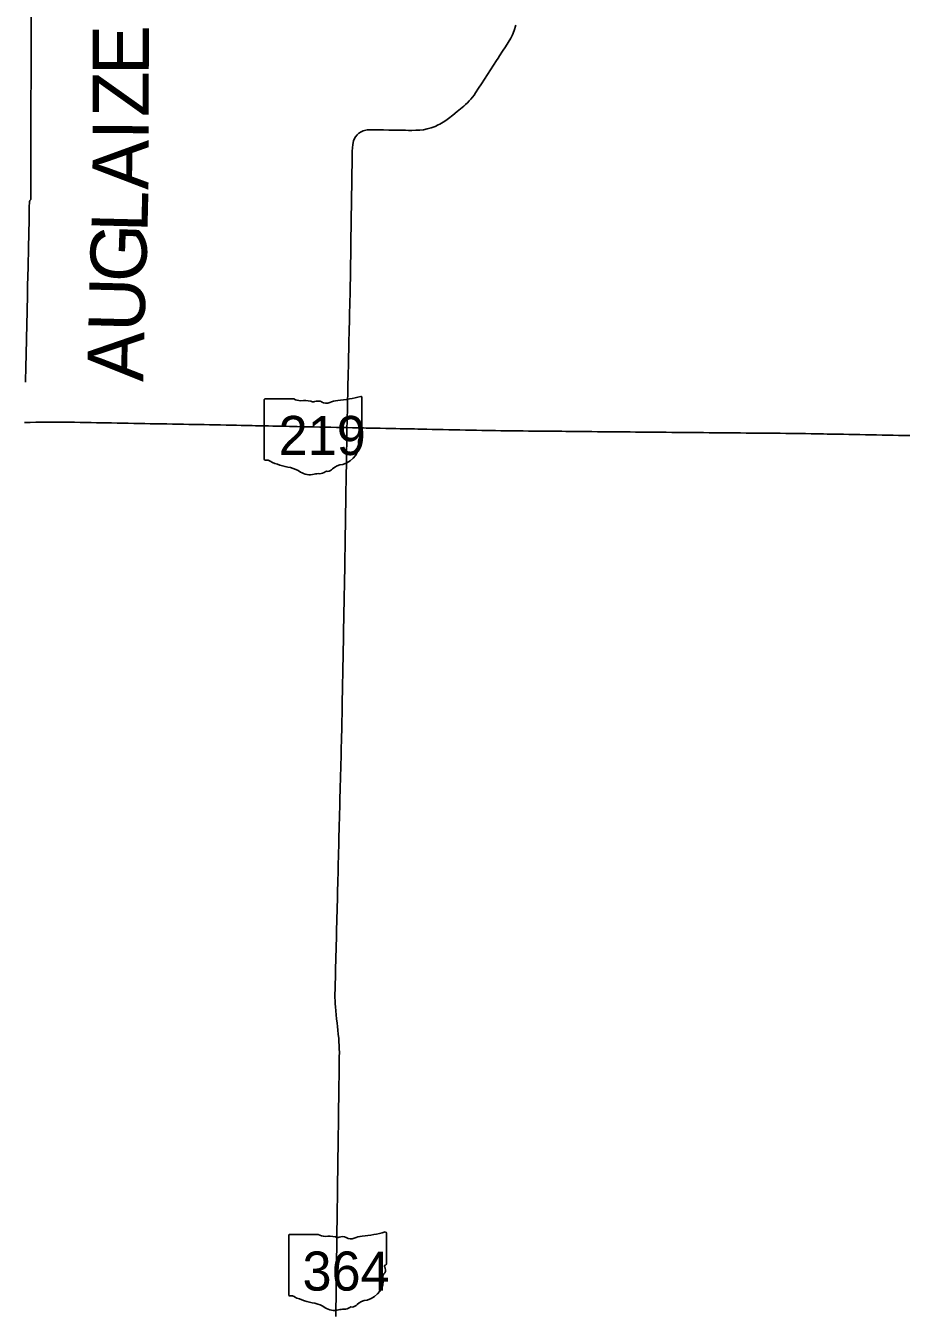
# Model space of a CAD drawing. Extents: x 0 to 34, y 0 to 22.
# Drawn here: x 4.2041 to 4.4563, y 19.2422 to 19.6111 of the extents above; entities that cross this region are included whole.
import ezdxf

# ---------------------------------------------------------------- set-up
doc = ezdxf.new("R2010")
doc.units = 0
for name, color, linetype in [('GM_X_County', 7, 'Continuous'), ('GM_X_County_Text', 7, 'Continuous'), ('GM_X_State_Location', 7, 'Continuous'), ('GM_X_State_Route', 7, 'Continuous'), ('GM_X_State_Shield', 7, 'Continuous')]:
    doc.layers.add(name, color=color, linetype=linetype)

msp = doc.modelspace()

# ---------------------------------------------------------------- linework, layer by layer
at = {"layer": 'GM_X_County'}
for points in [[(4.20566, 19.62427), (4.20556, 19.5614), (4.20547, 19.56133), (4.2054, 19.56127), (4.20535, 19.56121), (4.20531, 19.56115), (4.20527, 19.56107), (4.20523, 19.56097), (4.20519, 19.56086), (4.20517, 19.56076), (4.20515, 19.56061), (4.20512, 19.56041), (4.2051, 19.56013), (4.20508, 19.5598), (4.20502, 19.55558), (4.2049, 19.54762), (4.2048, 19.54209), (4.2046, 19.53666), (4.20455, 19.53397), (4.20448, 19.52949), (4.2044, 19.52543), (4.20431, 19.52169), (4.20417, 19.51684), (4.2041, 19.51363), (4.20398, 19.50904)], [(4.20398, 19.50904), (4.2041, 19.51363), (4.20417, 19.51684), (4.20431, 19.52169), (4.2044, 19.52543), (4.20448, 19.52949), (4.20455, 19.53397), (4.2046, 19.53666), (4.2048, 19.54209), (4.2049, 19.54762), (4.20502, 19.55558), (4.20508, 19.5598), (4.2051, 19.56013), (4.20512, 19.56041), (4.20515, 19.56061), (4.20517, 19.56076), (4.20519, 19.56086), (4.20523, 19.56097), (4.20527, 19.56107), (4.20531, 19.56115), (4.20535, 19.56121), (4.2054, 19.56127), (4.20547, 19.56133), (4.20556, 19.5614), (4.20566, 19.62427)]]:
    msp.add_lwpolyline(points, dxfattribs=at)
at = {"layer": 'GM_X_State_Route'}
for points in [[(4.29608, 19.49608), (4.29611, 19.49766), (4.29615, 19.49924), (4.29619, 19.50082), (4.29622, 19.50241), (4.29626, 19.50399), (4.29629, 19.50557), (4.29633, 19.50715), (4.29637, 19.50873), (4.2964, 19.51031), (4.29644, 19.5119), (4.29648, 19.51348), (4.29651, 19.51506), (4.29655, 19.51664), (4.29659, 19.51822), (4.29662, 19.5198), (4.29666, 19.52139), (4.29669, 19.52297), (4.29673, 19.52455), (4.29677, 19.52613), (4.2968, 19.52771), (4.29684, 19.52929), (4.29687, 19.53087), (4.29691, 19.53246), (4.29695, 19.53404), (4.29698, 19.53562), (4.29702, 19.53711), (4.29705, 19.53861), (4.29707, 19.54019), (4.2971, 19.54177), (4.29712, 19.54336), (4.29714, 19.54494), (4.29716, 19.54652), (4.29718, 19.5481), (4.29721, 19.54968), (4.29723, 19.55127), (4.29725, 19.55285), (4.29727, 19.55443), (4.29729, 19.55601), (4.29732, 19.55759), (4.29733, 19.55878), (4.29735, 19.55996), (4.29738, 19.56154), (4.2974, 19.56312), (4.29743, 19.5647), (4.29746, 19.56628), (4.29748, 19.56787), (4.29751, 19.56945), (4.29754, 19.57101), (4.29756, 19.57258), (4.29759, 19.5739), (4.29761, 19.57523), (4.29769, 19.57618), (4.29777, 19.57714), (4.29796, 19.57814), (4.2982, 19.57886), (4.29848, 19.57934), (4.29896, 19.57991), (4.29945, 19.58039), (4.30013, 19.58079), (4.30076, 19.58105), (4.30147, 19.58122), (4.30186, 19.5813), (4.30241, 19.58133), (4.30335, 19.58133), (4.30493, 19.58131), (4.30651, 19.58129), (4.30809, 19.58126), (4.30967, 19.58124), (4.31126, 19.58122), (4.31284, 19.5812), (4.31373, 19.58119), (4.31462, 19.58117), (4.31577, 19.58121), (4.31692, 19.58125), (4.31798, 19.58137), (4.31904, 19.58158), (4.32024, 19.58192), (4.3213, 19.5823), (4.32221, 19.58272), (4.32267, 19.58297), (4.32366, 19.58352), (4.32441, 19.58403), (4.32517, 19.58454), (4.32639, 19.58554), (4.32761, 19.58654), (4.32857, 19.58733), (4.32952, 19.58811), (4.33007, 19.58859), (4.3306, 19.58909), (4.33111, 19.58961), (4.33159, 19.59015), (4.33205, 19.59071), (4.33248, 19.5913), (4.33289, 19.5919), (4.33375, 19.59322), (4.33462, 19.59455), (4.33548, 19.59588), (4.33634, 19.5972), (4.3372, 19.59853), (4.33806, 19.59986), (4.33892, 19.60118), (4.33937, 19.60187), (4.33981, 19.60255), (4.34066, 19.60382), (4.3415, 19.60509), (4.34226, 19.60636), (4.34302, 19.60762), (4.34351, 19.60849), (4.34397, 19.6098), (4.34447, 19.6113)], [(4.20376, 19.49757), (4.20534, 19.49758), (4.20693, 19.4976), (4.20851, 19.49761), (4.21009, 19.49762), (4.21167, 19.49763), (4.21325, 19.49764), (4.21406, 19.49765), (4.21486, 19.49765), (4.21645, 19.49763), (4.21803, 19.4976), (4.21961, 19.49757), (4.22119, 19.49754), (4.22277, 19.49751), (4.22436, 19.49748), (4.22594, 19.49745), (4.2273, 19.49743), (4.22866, 19.4974), (4.23024, 19.49737), (4.23182, 19.49734), (4.23341, 19.49732), (4.23499, 19.49729), (4.23657, 19.49726), (4.23815, 19.49723), (4.23973, 19.4972), (4.24132, 19.49717), (4.2429, 19.49714), (4.24448, 19.49711), (4.24606, 19.49709), (4.24765, 19.49706), (4.24923, 19.49703), (4.25081, 19.497), (4.25219, 19.49697), (4.25357, 19.49695), (4.25516, 19.49692), (4.25674, 19.49688), (4.25832, 19.49685), (4.2599, 19.49682), (4.26148, 19.49679), (4.26306, 19.49676), (4.26441, 19.49673), (4.26575, 19.4967), (4.26733, 19.49667), (4.26891, 19.49664), (4.26984, 19.49662), (4.27077, 19.4966), (4.27235, 19.49657), (4.27359, 19.49654), (4.27483, 19.49651), (4.27641, 19.49648), (4.27799, 19.49645), (4.27957, 19.49642), (4.28068, 19.4964), (4.2818, 19.49637), (4.28338, 19.49634), (4.28427, 19.49632), (4.28515, 19.4963), (4.28673, 19.49627), (4.28831, 19.49624), (4.2899, 19.49621), (4.29148, 19.49617), (4.29306, 19.49614), (4.29457, 19.49611), (4.29608, 19.49608), (4.29766, 19.49605), (4.29924, 19.49601), (4.30082, 19.49598), (4.30162, 19.49596), (4.30242, 19.49595), (4.30401, 19.49592), (4.30559, 19.49588), (4.30717, 19.49585), (4.30875, 19.49582), (4.31003, 19.49579), (4.3113, 19.49576), (4.31289, 19.49573), (4.31447, 19.4957), (4.31542, 19.49568), (4.31638, 19.49566), (4.31735, 19.49564), (4.31893, 19.49561), (4.32051, 19.49557), (4.32209, 19.49554), (4.32367, 19.49551), (4.32525, 19.49547), (4.32683, 19.49544), (4.32842, 19.49541), (4.33, 19.49537), (4.33158, 19.49534), (4.33316, 19.49531), (4.33474, 19.49528), (4.33632, 19.49524), (4.33747, 19.49522), (4.33861, 19.4952), (4.34019, 19.49518), (4.34177, 19.49516), (4.34336, 19.49515), (4.34494, 19.49513), (4.34652, 19.49512), (4.3481, 19.4951), (4.34968, 19.49509), (4.35127, 19.49507), (4.35285, 19.49506), (4.35443, 19.49504), (4.35601, 19.49502), (4.35759, 19.49501), (4.35876, 19.495), (4.35992, 19.49499), (4.3615, 19.49497), (4.36308, 19.49495), (4.36467, 19.49494), (4.36625, 19.49492), (4.36783, 19.49491), (4.36941, 19.49489), (4.37078, 19.49488), (4.37215, 19.49487), (4.37373, 19.49485), (4.37531, 19.49483), (4.37625, 19.49483), (4.37719, 19.49482), (4.37877, 19.4948), (4.38, 19.49479), (4.38122, 19.49478), (4.38281, 19.49476), (4.38439, 19.49475), (4.38597, 19.49474), (4.38755, 19.49472), (4.38913, 19.49471), (4.3905, 19.4947), (4.39187, 19.49468), (4.39345, 19.49467), (4.39503, 19.49466), (4.39661, 19.49464), (4.3982, 19.49463), (4.39978, 19.49462), (4.40115, 19.4946), (4.40251, 19.49459), (4.4041, 19.49458), (4.40568, 19.49456), (4.40726, 19.49455), (4.40884, 19.49454), (4.41042, 19.49452), (4.41179, 19.49451), (4.41316, 19.4945), (4.41474, 19.49448), (4.41632, 19.49447), (4.41791, 19.49446), (4.41905, 19.49445), (4.42019, 19.49444), (4.42177, 19.49442), (4.42279, 19.49441), (4.4238, 19.49441), (4.42539, 19.49438), (4.4264, 19.49436), (4.42742, 19.49434), (4.429, 19.49431), (4.43002, 19.49429), (4.43104, 19.49428), (4.43262, 19.49425), (4.43364, 19.49423), (4.43465, 19.49421), (4.43623, 19.49418), (4.43725, 19.49416), (4.43827, 19.49415), (4.43985, 19.49412), (4.44144, 19.49409), (4.44302, 19.49406), (4.4446, 19.49403), (4.44618, 19.494), (4.44776, 19.49397), (4.44935, 19.49395), (4.45093, 19.49392), (4.45251, 19.49389), (4.45409, 19.49386), (4.45567, 19.49383), (4.45726, 19.49381)], [(4.29326, 19.32554), (4.29312, 19.32675), (4.29298, 19.32796), (4.29287, 19.32909), (4.29276, 19.33022), (4.29272, 19.33108), (4.29267, 19.33195), (4.29265, 19.33286), (4.29264, 19.33378), (4.29268, 19.33536), (4.29272, 19.33694), (4.29276, 19.33852), (4.2928, 19.34011), (4.29284, 19.34169), (4.29288, 19.34327), (4.29292, 19.34485), (4.29296, 19.34643), (4.293, 19.34801), (4.29304, 19.3496), (4.29308, 19.35118), (4.29312, 19.35276), (4.29316, 19.35434), (4.2932, 19.35592), (4.29324, 19.3575), (4.29328, 19.35909), (4.29332, 19.36067), (4.29336, 19.36225), (4.2934, 19.36383), (4.29344, 19.36541), (4.29347, 19.36683), (4.29351, 19.36825), (4.29355, 19.36983), (4.29359, 19.37141), (4.29363, 19.37299), (4.29367, 19.37458), (4.29371, 19.37616), (4.29375, 19.37774), (4.29379, 19.37932), (4.29384, 19.3809), (4.29388, 19.38248), (4.29392, 19.38407), (4.29396, 19.38565), (4.294, 19.38723), (4.29404, 19.38881), (4.29408, 19.39039), (4.29412, 19.39197), (4.29416, 19.39355), (4.2942, 19.39514), (4.29424, 19.39672), (4.29429, 19.3983), (4.29433, 19.39988), (4.29437, 19.40146), (4.29441, 19.40304), (4.29445, 19.40463), (4.29449, 19.40621), (4.29453, 19.40779), (4.29457, 19.40924), (4.29461, 19.41069), (4.29463, 19.41227), (4.29466, 19.41385), (4.29469, 19.41544), (4.29472, 19.41702), (4.29475, 19.4186), (4.29478, 19.42018), (4.29481, 19.42176), (4.29484, 19.42334), (4.29487, 19.42492), (4.2949, 19.42651), (4.29493, 19.42809), (4.29495, 19.42967), (4.29498, 19.43125), (4.29501, 19.43283), (4.29504, 19.43441), (4.29507, 19.436), (4.2951, 19.43758), (4.29513, 19.43916), (4.29516, 19.44074), (4.29519, 19.44232), (4.29522, 19.4439), (4.29525, 19.44549), (4.29528, 19.44707), (4.29531, 19.44865), (4.29534, 19.45023), (4.29536, 19.45176), (4.29539, 19.45328), (4.29542, 19.45487), (4.29544, 19.45645), (4.29547, 19.45803), (4.29549, 19.45961), (4.29552, 19.46119), (4.29554, 19.46278), (4.29557, 19.46436), (4.29559, 19.46594), (4.29562, 19.46752), (4.29565, 19.46911), (4.29567, 19.47069), (4.2957, 19.47227), (4.29572, 19.47385), (4.29575, 19.47543), (4.29577, 19.47702), (4.2958, 19.4786), (4.29582, 19.48018), (4.29585, 19.48176), (4.29587, 19.48334), (4.2959, 19.48493), (4.29592, 19.48651), (4.29595, 19.48809), (4.29597, 19.48967), (4.296, 19.49125), (4.29602, 19.49284), (4.29605, 19.49442), (4.29606, 19.49525), (4.29608, 19.49608)], [(4.29289, 19.24156), (4.29291, 19.24314), (4.29293, 19.24472), (4.29295, 19.24631), (4.29297, 19.24789), (4.29299, 19.24947), (4.29301, 19.25105), (4.29303, 19.25264), (4.29305, 19.25422), (4.29307, 19.2558), (4.2931, 19.25738), (4.29312, 19.25896), (4.29314, 19.26055), (4.29316, 19.26213), (4.29318, 19.26371), (4.2932, 19.26529), (4.29322, 19.26687), (4.29324, 19.26846), (4.29326, 19.27004), (4.29328, 19.27162), (4.2933, 19.2732), (4.29332, 19.27478), (4.29334, 19.27637), (4.29336, 19.27795), (4.29338, 19.27953), (4.2934, 19.28111), (4.29342, 19.28269), (4.29343, 19.28365), (4.29345, 19.28461), (4.29347, 19.28619), (4.29349, 19.28777), (4.29352, 19.28935), (4.29354, 19.29094), (4.29356, 19.29252), (4.29358, 19.2941), (4.29361, 19.29568), (4.29363, 19.29727), (4.29365, 19.29885), (4.29368, 19.30043), (4.2937, 19.30201), (4.29372, 19.30359), (4.29375, 19.30518), (4.29377, 19.30676), (4.29379, 19.30834), (4.29381, 19.30992), (4.29384, 19.3115), (4.29386, 19.31307), (4.29388, 19.31463), (4.29389, 19.31588), (4.2939, 19.31712), (4.29388, 19.31816), (4.29387, 19.31919), (4.29379, 19.32019), (4.29371, 19.3212), (4.2936, 19.32238), (4.29349, 19.32356), (4.29338, 19.32455), (4.29326, 19.32554)]]:
    msp.add_lwpolyline(points, dxfattribs=at)
at = {"layer": 'GM_X_State_Shield'}
for p, q in [((4.27239, 19.50402), (4.27239, 19.48704)), ((4.28086, 19.50431), (4.27267, 19.50431)), ((4.30036, 19.49585), (4.30036, 19.50473)), ((4.30036, 19.49585), (4.30036, 19.49585)), ((4.30736, 19.25658), (4.30736, 19.26547)), ((4.27939, 19.26476), (4.27939, 19.24777)), ((4.28786, 19.26505), (4.27967, 19.26505)), ((4.30736, 19.25659), (4.30736, 19.25658))]:
    msp.add_line(p, q, dxfattribs=at)
for centre, major_axis, start_param, end_param in [((4.27271, 19.50406), (0.000324, 0), 1.712693, 3.28349), ((4.28281, 19.50628), (0.00314, 0), 4.042523, 4.731795), ((4.28385, 19.49478), (0.01128, 0), 1.404758, 1.657858), ((4.28641, 19.50414), (0.000907, 0), 3.836095, 5.185415), ((4.28774, 19.50218), (0.00189, 0), 0.950623, 2.079405), ((4.29018, 19.50487), (0.00227, 0), 4.081561, 5.145723), ((4.29418, 19.49913), (0.00597, 0), 1.699011, 2.107814), ((4.2904, 19.52747), (0.02966, 0), 4.814394, 5.042369), ((4.30005, 19.50477), (0.000311, 0), 6.141152, 7.989035), ((4.30029, 19.4952), (0.000482, 0), 1.883978, 3.671073), ((4.29722, 19.49407), (0.00289, 0), 5.934695, 6.695948), ((4.30003, 19.49581), (0.000333, 0), 5.05454, 6.418171), ((4.29206, 19.491), (0.00742, 0), 5.101752, 6.440018), ((4.30148, 19.49213), (0.0021, 0), 2.387724, 3.262537), ((4.27271, 19.487), (0.000327, 0), 3.00124, 4.508301), ((4.27276, 19.48874), (0.00249, 0), 4.665946, 4.897461), ((4.27327, 19.48606), (0.0009, 0), 0.519207, 1.627899), ((4.28463, 19.50132), (0.02142, 0), 4.195997, 4.488961), ((4.27824, 19.47941), (0.0067, 0), 0.823519, 1.323587), ((4.28549, 19.48597), (0.00425, 0), 4.026481, 4.996735), ((4.28826, 19.4847), (0.00227, 0), 4.691044, 5.507374), ((4.29031, 19.48306), (0.000638, 0), 1.147584, 2.315152), ((4.29004, 19.48539), (0.0024, 0), 4.937069, 5.64225), ((4.29519, 19.48227), (0.00406, 0), 1.647645, 2.488434), ((4.28795, 19.4801), (0.00349, 0), 1.495662, 1.94098), ((4.2974, 19.2882), (0.02966, 0), 4.814394, 5.042369), ((4.30705, 19.26551), (0.000311, 0), 6.141152, 7.989035), ((4.27971, 19.26479), (0.000324, 0), 1.712693, 3.28349), ((4.28981, 19.26702), (0.00314, 0), 4.042523, 4.731795), ((4.29085, 19.25551), (0.01128, 0), 1.404758, 1.657858), ((4.29341, 19.26488), (0.000907, 0), 3.836095, 5.185415), ((4.29475, 19.26292), (0.00189, 0), 0.950623, 2.079405), ((4.29718, 19.26561), (0.00227, 0), 4.081561, 5.145723), ((4.30118, 19.25986), (0.00597, 0), 1.699011, 2.107814), ((4.30729, 19.25593), (0.000482, 0), 1.883978, 3.671073), ((4.30423, 19.25481), (0.00289, 0), 5.934695, 6.695948), ((4.30703, 19.25655), (0.000333, 0), 5.05454, 6.418171), ((4.29906, 19.25174), (0.00742, 0), 5.101752, 6.440018), ((4.30848, 19.25287), (0.0021, 0), 2.387724, 3.262537), ((4.27972, 19.24773), (0.000327, 0), 3.00124, 4.508301), ((4.27977, 19.24947), (0.00249, 0), 4.665946, 4.897461), ((4.28028, 19.24679), (0.0009, 0), 0.519207, 1.627899), ((4.29163, 19.26205), (0.02142, 0), 4.195997, 4.488961), ((4.28525, 19.24014), (0.0067, 0), 0.823519, 1.323587), ((4.2925, 19.24671), (0.00425, 0), 4.026481, 4.996735), ((4.29495, 19.24084), (0.00349, 0), 1.495662, 1.94098), ((4.29526, 19.24544), (0.00227, 0), 4.691044, 5.507374), ((4.29731, 19.24379), (0.000638, 0), 1.147584, 2.315152), ((4.29704, 19.24613), (0.0024, 0), 4.937069, 5.64225), ((4.30219, 19.243), (0.00406, 0), 1.647645, 2.488434)]:
    msp.add_ellipse(centre, major_axis=major_axis, ratio=0.8, start_param=start_param, end_param=end_param, dxfattribs=at)

# ---------------------------------------------------------------- texts
at = {"layer": 'GM_X_County_Text'}
for s, rotation, p in [('E', 89.8711, (4.23932, 19.59698)), ('Z', 89.9348, (4.23931, 19.58497)), ('I', 89.915, (4.2393, 19.57839)), ('A', 89.6811, (4.23922, 19.56412)), ('L', 88.6109, (4.23892, 19.55185)), ('G', 87.934, (4.23841, 19.53749)), ('U', 88.5242, (4.23804, 19.52333)), ('A', 88.6955, (4.23772, 19.50913))]:
    msp.add_text(s, height=0.01607, rotation=rotation, dxfattribs=at).set_placement(p)
at = {"layer": 'GM_X_State_Location'}
for s, p in [('s', (4.28606, 19.4944)), ('r', (4.28606, 19.4944)), ('s', (4.29306, 19.25513)), ('r', (4.29306, 19.25513))]:
    msp.add_text(s, height=0.0000161, dxfattribs=at).set_placement(p)
for s, p in [('219', (4.28039, 19.49323)), ('364', (4.28739, 19.25396))]:
    msp.add_text(s, height=0.0000161, rotation=0, dxfattribs=at).set_placement(p)
at = {"layer": 'GM_X_State_Shield'}
for s, p in [('219', (4.2765, 19.48823)), ('364', (4.28334, 19.24897))]:
    msp.add_text(s, height=0.011189, dxfattribs=at).set_placement(p)

doc.saveas('drawing.dxf')
